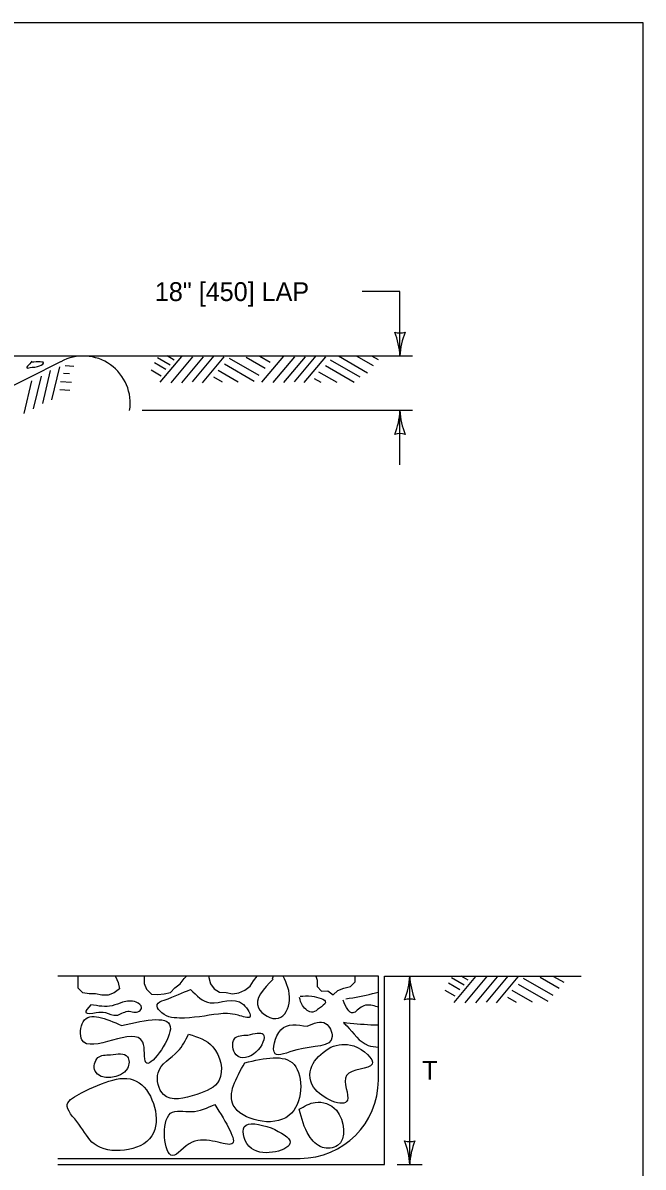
# Model space of a CAD drawing. Extents: x 49991.4 to 50021, y 49987.6 to 50011.4.
# Drawn here: x 50006.635 to 50008.615, y 50007.611 to 50011.263 of the extents above; entities that cross this region are included whole.
import ezdxf

# ---------------------------------------------------------------- set-up
doc = ezdxf.new("R2010")
doc.units = 0
for name, color, linetype in [('Level 1', 7, 'Continuous'), ('Level 2', 7, 'Continuous'), ('Level 3', 7, 'Continuous')]:
    doc.layers.add(name, color=color, linetype=linetype)

msp = doc.modelspace()

# ---------------------------------------------------------------- linework, layer by layer
at = {"layer": 'Level 1'}
for p, q in [((50003.3042, 50008.4558), (50006.7558, 50010.1815)), ((50005.7004, 50010.1996), (50007.8785, 50010.1996)), ((50006.6635, 50010.1836), (50006.657, 50010.1748)), ((50007.0914, 50010.1563), (50007.0553, 50010.1773)), ((50007.1053, 50010.1703), (50007.0648, 50010.1937)), ((50007.0729, 50010.1157), (50007.142, 50010.1981)), ((50007.1179, 50010.1867), (50007.0956, 50010.1996)), ((50007.1084, 50010.1144), (50007.1776, 50010.1968)), ((50007.1424, 50010.1144), (50007.2117, 50010.1968)), ((50007.1765, 50010.1169), (50007.2457, 50010.1996)), ((50007.2078, 50010.1144), (50007.2772, 50010.1968)), ((50007.373, 50010.1183), (50007.2784, 50010.173)), ((50007.389, 50010.1372), (50007.2944, 50010.1919)), ((50007.408, 50010.1598), (50007.3471, 50010.195)), ((50007.424, 50010.179), (50007.3914, 50010.1977)), ((50007.398, 50010.1161), (50007.4674, 50010.1985)), ((50007.4335, 50010.1148), (50007.5029, 50010.1973)), ((50007.4678, 50010.1148), (50007.5369, 50010.1973)), ((50007.5018, 50010.1175), (50007.5709, 50010.1999)), ((50007.5332, 50010.1148), (50007.6023, 50010.1973)), ((50007.7111, 50010.132), (50007.6163, 50010.1867)), ((50007.7347, 50010.145), (50007.642, 50010.1985)), ((50007.7537, 50010.1677), (50007.7002, 50010.1985)), ((50007.7697, 50010.1868), (50007.7492, 50010.1985)), ((50006.6691, 50010.0307), (50006.6941, 50010.1354)), ((50006.6983, 50010.0483), (50006.7234, 50010.153)), ((50006.7276, 50010.06), (50006.7525, 50010.1647)), ((50006.7838, 50010.1425), (50006.7644, 50010.1437)), ((50006.7975, 50010.1662), (50006.7701, 50010.1679)), ((50007.0758, 50010.1356), (50007.0444, 50010.1539)), ((50007.3225, 50010.116), (50007.258, 50010.1532)), ((50007.6377, 50010.1148), (50007.58, 50010.148)), ((50007.6921, 50010.1148), (50007.6003, 50010.1677)), ((50006.6386, 50010.0155), (50006.6636, 50010.1201)), ((50006.7897, 50010.1148), (50006.755, 50010.117)), ((50007.2718, 50010.1157), (50007.2441, 50010.1316)), ((50007.5865, 50010.1148), (50007.5662, 50010.1265)), ((50006.7842, 50010.0897), (50006.7523, 50010.0916)), ((50007.7696, 50008.2203), (50006.7468, 50008.2203)), ((50007.4336, 50008.2203), (50007.4301, 50008.2107)), ((50008.0299, 50008.177), (50007.9938, 50008.198)), ((50008.0438, 50008.191), (50008.0033, 50008.2144)), ((50008.0114, 50008.1364), (50008.0805, 50008.2188)), ((50008.0564, 50008.2074), (50008.0341, 50008.2203)), ((50008.0469, 50008.1351), (50008.1161, 50008.2175)), ((50008.0809, 50008.1351), (50008.1502, 50008.2175)), ((50008.115, 50008.1376), (50008.1842, 50008.2203)), ((50008.1463, 50008.1351), (50008.2157, 50008.2175)), ((50008.3275, 50008.1579), (50008.2329, 50008.2126)), ((50008.3465, 50008.1805), (50008.2856, 50008.2157)), ((50008.3625, 50008.1997), (50008.3299, 50008.2184)), ((50008.0143, 50008.1563), (50007.9829, 50008.1746)), ((50008.261, 50008.1367), (50008.1965, 50008.1739)), ((50008.3115, 50008.139), (50008.2169, 50008.1937)), ((50008.2103, 50008.1364), (50008.1826, 50008.1523))]:
    msp.add_line(p, q, dxfattribs=at)
msp.add_lwpolyline([(50008.6146, 50011.2628), (50000.3356, 50011.2628), (50000.3356, 50000.0624), (50008.6146, 50000.0624)], close=True, dxfattribs=at)
for points in [[(50006.7468, 50007.6186), (50007.7896, 50007.6186), (50007.7896, 50008.2203), (50008.4168, 50008.2203)], [(50006.9289, 50008.2203), (50006.9302, 50008.2189), (50006.9391, 50008.1998), (50006.9429, 50008.1794), (50006.9264, 50008.1666), (50006.9072, 50008.159), (50006.8868, 50008.159), (50006.8664, 50008.1641), (50006.8461, 50008.1641), (50006.8257, 50008.1666), (50006.8116, 50008.1819), (50006.8116, 50008.2023), (50006.8116, 50008.2203)], [(50007.022, 50008.2203), (50007.022, 50008.2176), (50007.022, 50008.1972), (50007.0296, 50008.1781), (50007.0449, 50008.1628), (50007.0653, 50008.1615), (50007.0857, 50008.1641), (50007.1061, 50008.1679), (50007.1201, 50008.1832), (50007.1367, 50008.1959), (50007.1495, 50008.2125), (50007.1566, 50008.2203)], [(50007.2285, 50008.2203), (50007.2285, 50008.2163), (50007.2336, 50008.1959), (50007.2451, 50008.1794), (50007.2629, 50008.1692), (50007.2833, 50008.1679), (50007.3037, 50008.1641), (50007.3241, 50008.1666), (50007.3432, 50008.1755), (50007.3598, 50008.1883), (50007.3713, 50008.2049), (50007.3831, 50008.2203)], [(50007.5697, 50008.2203), (50007.574, 50008.2074), (50007.574, 50008.187), (50007.588, 50008.1717), (50007.6084, 50008.173), (50007.625, 50008.1602), (50007.6403, 50008.1743), (50007.6594, 50008.1819), (50007.681, 50008.187), (50007.6951, 50008.2023), (50007.6951, 50008.2203)], [(50007.7696, 50007.8886), (50007.7696, 50008.2203)], [(50006.7468, 50007.6386), (50007.5196, 50007.6386)]]:
    msp.add_lwpolyline(points, dxfattribs=at)
for centre, radius, start, end in [((50006.8273, 50010.0494), 0.1501, 350.7702, 118.4505), ((50007.5196, 50007.8886), 0.25, 270, 0)]:
    msp.add_arc(centre, radius, start, end, dxfattribs=at)
for points in [[(50006.657, 50010.1748), (50006.6475, 50010.1621), (50006.6644, 50010.1639)], [(50006.6644, 50010.1639), (50006.6815, 50010.1656), (50006.701, 50010.1764), (50006.6615, 50010.18)], [(50007.4335, 50008.2107), (50007.3866, 50008.1187), (50007.4511, 50008.0857), (50007.4856, 50008.1433), (50007.4658, 50008.2203)], [(50007.1694, 50008.178), (50007.0863, 50008.1438), (50007.0633, 50008.1294), (50007.072, 50008.1091), (50007.1349, 50008.0863), (50007.2593, 50008.0991), (50007.3218, 50008.0956), (50007.3591, 50008.0893), (50007.3387, 50008.1294), (50007.2327, 50008.1352), (50007.1694, 50008.178)], [(50007.6661, 50008.148), (50007.7511, 50008.1643), (50007.7696, 50008.1695)], [(50006.852, 50008.1288), (50006.9201, 50008.1259), (50006.9533, 50008.1369), (50006.9963, 50008.1369), (50007.0138, 50008.1201), (50007.0062, 50008.1079), (50006.9695, 50008.1079), (50006.9335, 50008.0951), (50006.8986, 50008.1038), (50006.8683, 50008.1038), (50006.8357, 50008.1038), (50006.852, 50008.1288)], [(50007.5195, 50008.1561), (50007.5573, 50008.1561), (50007.6004, 50008.1364), (50007.5812, 50008.1177), (50007.5602, 50008.1055), (50007.5271, 50008.1265), (50007.5178, 50008.1515)], [(50007.7696, 50008.1208), (50007.7615, 50008.1236), (50007.7185, 50008.1236), (50007.6882, 50008.1026), (50007.6568, 50008.1433)], [(50006.9501, 50008.0625), (50006.8278, 50008.0748), (50006.8235, 50008.0166), (50007.0174, 50008.0098), (50007.027, 50007.9447), (50007.1056, 50008.0514), (50006.9501, 50008.0625)], [(50007.5421, 50008.0601), (50007.4583, 50008.0488), (50007.4401, 50007.9726), (50007.5093, 50007.9852), (50007.6221, 50008.0274), (50007.6012, 50008.0695), (50007.5421, 50008.0601)], [(50007.6581, 50008.0718), (50007.6686, 50008.0613), (50007.7371, 50007.9992), (50007.7696, 50007.9931)], [(50007.7696, 50008.0635), (50007.7458, 50008.0642), (50007.6581, 50008.0718)], [(50007.164, 50008.0347), (50007.1293, 50007.9803), (50007.0663, 50007.9114), (50007.0837, 50007.8426), (50007.1898, 50007.8426), (50007.2615, 50007.8883), (50007.2412, 50007.9945), (50007.164, 50008.0347)], [(50007.3533, 50008.0319), (50007.3101, 50008.0203), (50007.3159, 50007.9686), (50007.3789, 50007.9774), (50007.402, 50008.0347), (50007.3533, 50008.0319)], [(50007.618, 50007.9938), (50007.5609, 50007.941), (50007.5625, 50007.8663), (50007.6708, 50007.8238), (50007.668, 50007.903), (50007.75, 50007.9393), (50007.6909, 50007.9975), (50007.618, 50007.9938)], [(50006.9144, 50007.9686), (50006.8742, 50007.96), (50006.8653, 50007.917), (50006.9688, 50007.9258), (50006.9688, 50007.9629), (50006.9144, 50007.9686)], [(50007.3432, 50007.9435), (50007.3065, 50007.8081), (50007.4841, 50007.7752), (50007.5003, 50007.9381), (50007.3432, 50007.9435)], [(50006.8224, 50007.8481), (50006.7767, 50007.8109), (50006.8137, 50007.7476), (50006.8625, 50007.6846), (50007.0462, 50007.7104), (50007.006, 50007.8798), (50006.8224, 50007.8481)], [(50007.2472, 50007.8109), (50007.1724, 50007.7877), (50007.1065, 50007.7823), (50007.1124, 50007.6476), (50007.1752, 50007.6903), (50007.3017, 50007.6846), (50007.2472, 50007.8109)], [(50007.5172, 50007.7953), (50007.5483, 50007.7107), (50007.591, 50007.6735), (50007.6386, 50007.6791), (50007.6356, 50007.7919), (50007.5682, 50007.8174), (50007.5172, 50007.7953)], [(50007.4278, 50007.7362), (50007.3417, 50007.7391), (50007.3645, 50007.6704), (50007.4881, 50007.6903), (50007.4278, 50007.7362)]]:
    msp.add_spline(points, degree=3, dxfattribs=at)
at = {"layer": 'Level 3'}
for p, q in [((50007.8385, 50010.405), (50007.7174, 50010.405)), ((50007.8385, 50010.1996), (50007.8385, 50010.405)), ((50007.8785, 50010.0254), (50007.0155, 50010.0254)), ((50007.8385, 50009.8519), (50007.8385, 50010.0254)), ((50007.8696, 50007.6186), (50007.8696, 50008.2203)), ((50007.8296, 50007.6186), (50007.9096, 50007.6186))]:
    msp.add_line(p, q, dxfattribs=at)
for centre, radius, start, end in [((50007.8385, 50010.3278), 0.0548, 252.1388, 287.8612), ((50007.6057, 50010.1881), 0.233, 2.8273, 22.0772), ((50008.0606, 50010.1904), 0.2223, 157.456, 177.6395), ((50007.6163, 50010.0345), 0.2223, 337.456, 357.6395), ((50008.0712, 50010.0368), 0.233, 182.8273, 202.0772), ((50007.8385, 50009.8971), 0.0548, 72.1388, 107.8612), ((50007.6475, 50008.2294), 0.2223, 337.456, 357.6395), ((50008.1023, 50008.2318), 0.233, 182.8273, 202.0772), ((50007.8696, 50008.0921), 0.0548, 72.1388, 107.8612), ((50007.8696, 50007.7468), 0.0548, 252.1388, 287.8612), ((50007.6369, 50007.6071), 0.233, 2.8273, 22.0772), ((50008.0917, 50007.6094), 0.2223, 157.456, 177.6395)]:
    msp.add_arc(centre, radius, start, end, dxfattribs=at)

# ---------------------------------------------------------------- texts
at = {"layer": 'Level 2'}
for s, p in [('18" [450] LAP', (50007.0561, 50010.375)), ('T', (50007.9096, 50007.8894))]:
    msp.add_text(s, height=0.06, dxfattribs=at).set_placement(p)

doc.saveas('drawing.dxf')
